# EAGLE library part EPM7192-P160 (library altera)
EPM7192E MAX 7000 family
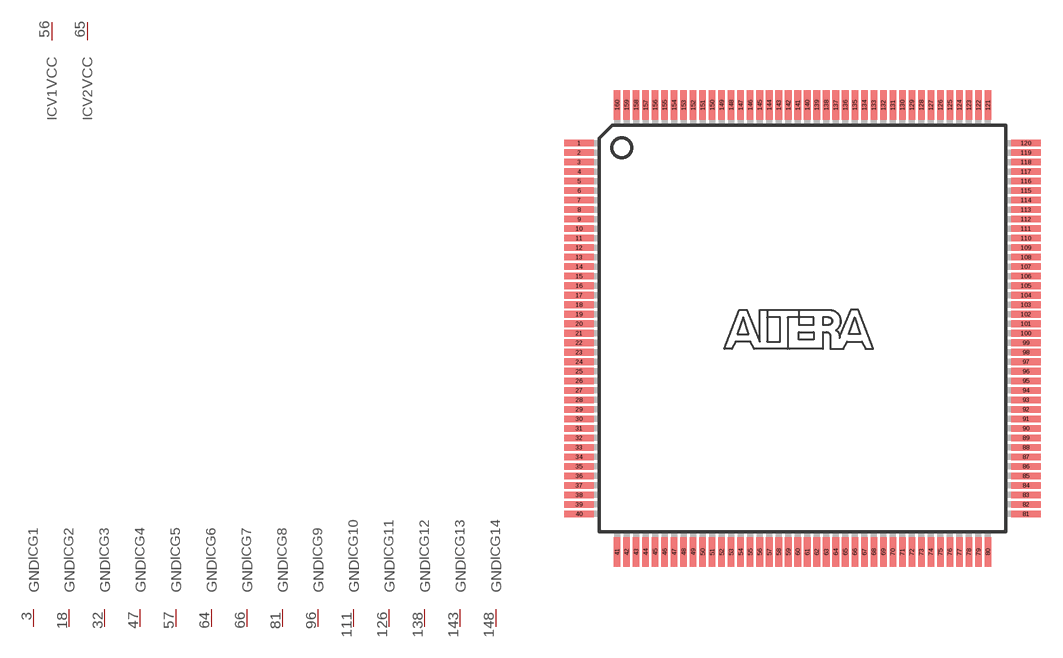
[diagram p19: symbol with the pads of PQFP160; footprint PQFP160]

Designator prefix IC; gates G1=GND G2=GND G3=GND G4=GND G5=GND G6=GND G7=GND G8=GND G9=GND G10=GND G11=GND G12=GND G13=GND G14=GND V1=VCCINT V2=VCCINT V3=VCCINT V4=VCCINT VO1=VCCIO VO2=VCCIO VO3=VCCIO VO4=VCCIO VO5=VCCIO VO6=VCCIO VO7=VCCIO VO8=VCCIO VO9=VCCIO VO10=VCCIO G=7192 NC1=NC NC2=NC NC3=NC NC4=NC NC5=NC NC6=NC NC7=NC NC8=NC

## EPM7192-P160 (MPN: EPM7192SQC160-10N; OC_FARNELL: 1549438; OC_NEWARK: 51R9820)  [PQFP160]
1  NC1:NC  nc
2  G:IO25
3  G1:GND  pwr
4  G:IO24
5  G:IO22
6  G:IO21
7  G:IO19
8  G:IO17
9  G:IO48
10  VO1:VCCIO  pwr
11  NC2:NC  nc
12  G:IO46
13  G:IO45
14  G:IO43
15  G:IO41
16  G:IO40
17  G:IO38
18  G2:GND  pwr
19  G:IO37
20  G:IO35
21  G:IO33
22  G:IO64
23  G:IO62
24  G:IO61
25  VO2:VCCIO  pwr
26  G:IO59
27  G:IO57
28  G:IO56
29  G:IO54
30  G:IO53
31  G:IO51
32  G3:GND  pwr
33  G:IO49
34  G:IO80
35  G:IO78
36  G:IO77
37  G:IO75
38  G:IO73
39  NC3:NC  nc
40  VO3:VCCIO  pwr
41  G:IO72
42  G:IO70
43  G:IO69
44  G:IO67
45  G:IO65
46  G:IO96
47  G4:GND  pwr
48  G:IO94
49  G:IO93
50  G:IO91
51  G:IO89
52  G:IO88
53  G:IO86
54  NC4:NC  nc
55  VO4:VCCIO  pwr
56  V1:VCC  pwr
57  G5:GND  pwr
58  G:IO85
59  G:IO83
60  G:IO81
61  G:IO97
62  G:IO99
63  G:IO101
64  G6:GND  pwr
65  V2:VCC  pwr
66  G7:GND  pwr
67  NC5:NC  nc
68  G:IO102
69  G:IO104
70  G:IO105
71  G:IO107
72  G:IO109
73  G:IO110
74  VO5:VCCIO  pwr
75  G:IO112
76  G:IO113
77  G:IO115
78  G:IO117
79  G:IO118
80  G:IO120
81  G8:GND  pwr
82  NC6:NC  nc
83  G:IO121
84  G:IO123
85  G:IO125
86  G:IO126
87  G:IO128
88  G:IO129
89  VO6:VCCIO  pwr
90  G:IO131
91  G:IO133
92  G:IO134
93  G:IO136
94  G:IO137
95  G:IO139
96  G9:GND  pwr
97  G:IO141
98  G:IO142
99  G:IO144
100  G:IO145
101  G:IO147
102  G:IO149
103  VO7:VCCIO  pwr
104  G:IO150
105  G:IO152
106  G:IO153
107  G:IO155
108  G:IO157
109  G:IO158
110  NC7:NC  nc
111  G10:GND  pwr
112  G:IO160
113  G:IO161
114  G:IO163
115  G:IO165
116  G:IO166
117  G:IO168
118  VO8:VCCIO  pwr
119  G:IO169
120  NC8:NC  nc
121  G:IO171
122  G:IO173
123  G:IO174
124  G:IO176
125  G:IO177
126  G11:GND  pwr
127  G:IO179
128  G:IO181
129  G:IO182
130  G:IO184
131  G:IO185
132  G:IO187
133  VO9:VCCIO  pwr
134  G:IO189
135  G:IO190
136  G:IO192
137  V3:VCC  pwr
138  G12:GND  pwr
139  G:GCLK1  in
140  G:OE1  in
141  G:GCLR/  in
142  G:OE2-GCLK2  in
143  G13:GND  pwr
144  V4:VCC  pwr
145  G:IO16
146  G:IO14
147  G:IO13
148  G14:GND  pwr
149  G:IO11
150  G:IO9
151  G:IO8
152  G:IO6
153  G:IO5
154  G:IO3
155  VO10:VCCIO  pwr
156  G:IO1
157  G:IO32
158  G:IO30
159  G:IO29
160  G:IO27

## Footprint PQFP160 (pad centres in mm)
Plastic Quad Flat Pack
smd 2 x 0.45: 1 -15.275,12.675; 2 -15.275,12.025; 3 -15.275,11.375; 4 -15.275,10.725; 5 -15.275,10.075; 6 -15.275,9.425; 7 -15.275,8.775; 8 -15.275,8.125; 9 -15.275,7.475; 10 -15.275,6.825; 11 -15.275,6.175; 12 -15.275,5.525; 13 -15.275,4.875; 14 -15.275,4.225; 15 -15.275,3.575; 16 -15.275,2.925; 17 -15.275,2.275; 18 -15.275,1.625; 19 -15.275,0.975; 20 -15.275,0.325; 21 -15.275,-0.325; 22 -15.275,-0.975; 23 -15.275,-1.625; 24 -15.275,-2.275; 25 -15.275,-2.925; 26 -15.275,-3.575; 27 -15.275,-4.225; 28 -15.275,-4.875; 29 -15.275,-5.525; 30 -15.275,-6.175; 31 -15.275,-6.825; 32 -15.275,-7.475; 33 -15.275,-8.125; 34 -15.275,-8.775; 35 -15.275,-9.425; 36 -15.275,-10.075; 37 -15.275,-10.725; 38 -15.275,-11.375; 39 -15.275,-12.025; 40 -15.275,-12.675; 81 15.275,-12.675; 82 15.275,-12.025; 83 15.275,-11.375; 84 15.275,-10.725; 85 15.275,-10.075; 86 15.275,-9.425; 87 15.275,-8.775; 88 15.275,-8.125; 89 15.275,-7.475; 90 15.275,-6.825; 91 15.275,-6.175; 92 15.275,-5.525; 93 15.275,-4.875; 94 15.275,-4.225; 95 15.275,-3.575; 96 15.275,-2.925; 97 15.275,-2.275; 98 15.275,-1.625; 99 15.275,-0.975; 100 15.275,-0.325; 101 15.275,0.325; 102 15.275,0.975; 103 15.275,1.625; 104 15.275,2.275; 105 15.275,2.925; 106 15.275,3.575; 107 15.275,4.225; 108 15.275,4.875; 109 15.275,5.525; 110 15.275,6.175; 111 15.275,6.825; 112 15.275,7.475; 113 15.275,8.125; 114 15.275,8.775; 115 15.275,9.425; 116 15.275,10.075; 117 15.275,10.725; 118 15.275,11.375; 119 15.275,12.025; 120 15.275,12.675
smd 0.45 x 2: 41 -12.675,-15.275; 42 -12.025,-15.275; 43 -11.375,-15.275; 44 -10.725,-15.275; 45 -10.075,-15.275; 46 -9.425,-15.275; 47 -8.775,-15.275; 48 -8.125,-15.275; 49 -7.475,-15.275; 50 -6.825,-15.275; 51 -6.175,-15.275; 52 -5.525,-15.275; 53 -4.875,-15.275; 54 -4.225,-15.275; 55 -3.575,-15.275; 56 -2.925,-15.275; 57 -2.275,-15.275; 58 -1.625,-15.275; 59 -0.975,-15.275; 60 -0.325,-15.275; 61 0.325,-15.275; 62 0.975,-15.275; 63 1.625,-15.275; 64 2.275,-15.275; 65 2.925,-15.275; 66 3.575,-15.275; 67 4.225,-15.275; 68 4.875,-15.275; 69 5.525,-15.275; 70 6.175,-15.275; 71 6.825,-15.275; 72 7.475,-15.275; 73 8.125,-15.275; 74 8.775,-15.275; 75 9.425,-15.275; 76 10.075,-15.275; 77 10.725,-15.275; 78 11.375,-15.275; 79 12.025,-15.275; 80 12.675,-15.275; 121 12.675,15.275; 122 12.025,15.275; 123 11.375,15.275; 124 10.725,15.275; 125 10.075,15.275; 126 9.425,15.275; 127 8.775,15.275; 128 8.125,15.275; 129 7.475,15.275; 130 6.825,15.275; 131 6.175,15.275; 132 5.525,15.275; 133 4.875,15.275; 134 4.225,15.275; 135 3.575,15.275; 136 2.925,15.275; 137 2.275,15.275; 138 1.625,15.275; 139 0.975,15.275; 140 0.325,15.275; 141 -0.325,15.275; 142 -0.975,15.275; 143 -1.625,15.275; 144 -2.275,15.275; 145 -2.925,15.275; 146 -3.575,15.275; 147 -4.225,15.275; 148 -4.875,15.275; 149 -5.525,15.275; 150 -6.175,15.275; 151 -6.825,15.275; 152 -7.475,15.275; 153 -8.125,15.275; 154 -8.775,15.275; 155 -9.425,15.275; 156 -10.075,15.275; 157 -10.725,15.275; 158 -11.375,15.275; 159 -12.025,15.275; 160 -12.675,15.275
